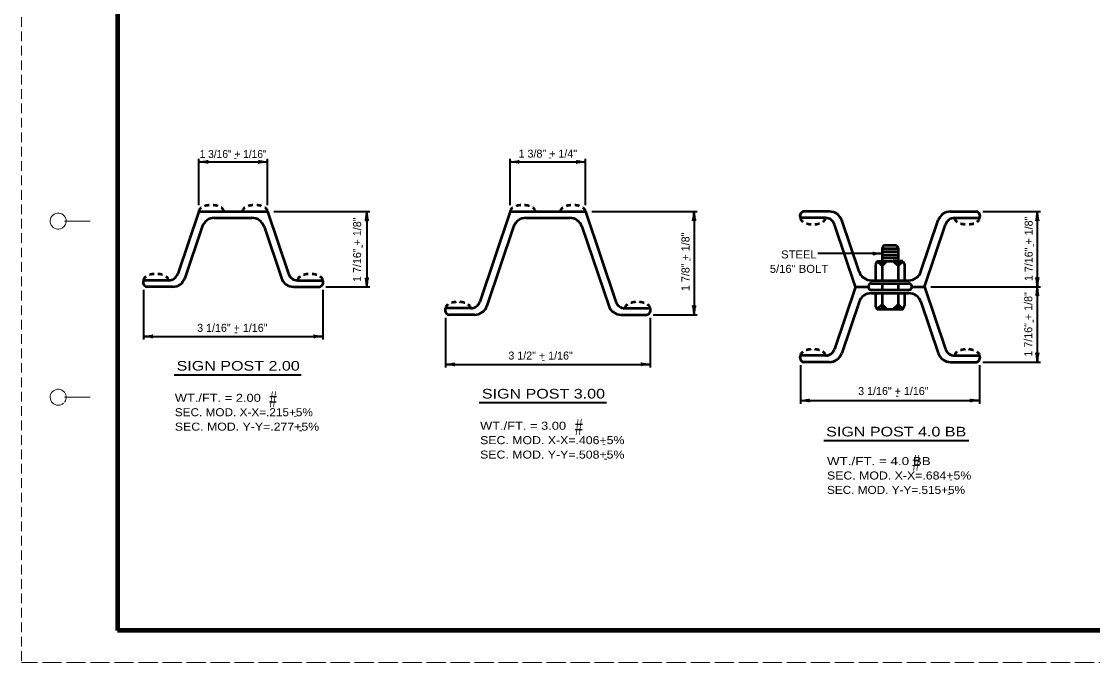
# Model space of a CAD drawing. Extents: x -2 to 678, y -1 to 439.
# Drawn here: x -1.8 to 332.9, y -0.7 to 199.5 of the extents above; entities that cross this region are included whole.
import ezdxf
from ezdxf.enums import TextEntityAlignment as Align

# ---------------------------------------------------------------- set-up
doc = ezdxf.new("R2010")
doc.units = 0
for name, pattern in [('LONG_DASHED', [7.5, 6, -1.5]), ('MEDIUM_DASHED', [4.5, 3, -1.5]), ('SHORT_DASHED', [2.7, 1.5, -1.2])]:
    doc.linetypes.add(name, pattern=pattern)
doc.layers.add('1', color=7, linetype='Continuous', lineweight=53)
doc.layers.add('61', color=7, linetype='Continuous', lineweight=35)

msp = doc.modelspace()

# ---------------------------------------------------------------- linework, layer by layer
at = {"layer": '1', "linetype": 'MEDIUM_DASHED', "lineweight": 13}
msp.add_line((-1.693, 439.301), (-1.753, -0.739), dxfattribs=at)
at = {"layer": '1', "lineweight": 35}
for p, q in [((53.628, 142.102), (53.628, 156.602)), ((53.628, 155.602), (75.128, 155.602)), ((75.128, 142.102), (75.128, 156.602)), ((150.929, 142.102), (150.929, 156.602)), ((150.929, 155.602), (174.429, 155.602)), ((174.429, 142.102), (174.429, 156.602)), ((77.128, 140.102), (107.128, 140.102)), ((106.128, 140.102), (106.128, 116.57)), ((176.429, 140.102), (209.37, 140.102)), ((208.37, 140.102), (208.37, 107.848)), ((298.576, 140.102), (316.576, 140.102)), ((267.076, 126.95), (247.023, 126.95)), ((36.378, 115.602), (36.378, 100.102)), ((92.378, 115.602), (92.378, 100.102)), ((93.378, 116.57), (107.128, 116.57)), ((282.326, 116.602), (316.576, 116.602)), ((195.62, 107.848), (209.37, 107.848)), ((130.738, 106.88), (130.738, 91.38)), ((194.62, 106.88), (194.62, 91.38)), ((36.378, 101.102), (92.378, 101.102)), ((130.738, 92.38), (194.62, 92.38)), ((241.576, 92.102), (241.576, 80.102)), ((297.576, 92.102), (297.576, 80.102)), ((298.576, 93.102), (316.576, 93.102)), ((241.576, 81.102), (297.576, 81.102))]:
    msp.add_line(p, q, dxfattribs=at)
at = {"layer": '1'}
for p, q in [((53.628, 140.102), (47.067, 120.644)), ((53.628, 140.102), (75.128, 140.102)), ((58.501, 138.102), (70.256, 138.102)), ((75.128, 140.102), (81.69, 120.644)), ((150.929, 140.102), (141.426, 111.922)), ((150.929, 140.102), (174.429, 140.102)), ((155.801, 138.102), (169.556, 138.102)), ((174.429, 140.102), (183.932, 111.922)), ((249.422, 138.102), (241.576, 138.102)), ((250.704, 140.102), (242.576, 140.102)), ((259.909, 121.324), (254.494, 137.38)), ((279.244, 121.324), (284.659, 137.38)), ((288.449, 140.102), (296.576, 140.102)), ((289.731, 138.102), (297.576, 138.102)), ((54.71, 135.38), (49.296, 119.324)), ((74.046, 135.38), (79.46, 119.324)), ((152.011, 135.38), (143.656, 110.602)), ((173.347, 135.38), (181.702, 110.602)), ((258.826, 116.602), (252.265, 136.061)), ((280.326, 116.602), (286.888, 136.061)), ((267.576, 129.602), (267.076, 128.602)), ((267.076, 128.602), (272.076, 128.602)), ((267.076, 127.602), (272.076, 127.602)), ((267.576, 129.602), (271.576, 129.602)), ((271.576, 129.602), (272.076, 128.602)), ((265.576, 124.602), (265.076, 123.602)), ((265.576, 124.602), (273.576, 124.602)), ((267.076, 126.602), (272.076, 126.602)), ((267.076, 125.602), (271.853, 125.602)), ((272.045, 125.602), (272.076, 125.602)), ((273.576, 124.602), (274.076, 123.602)), ((265.076, 123.602), (265.076, 118.602)), ((274.076, 123.602), (274.076, 118.602)), ((44.224, 118.602), (36.378, 118.602)), ((84.533, 118.602), (92.378, 118.602)), ((263.699, 118.602), (275.454, 118.602)), ((263.826, 117.602), (275.326, 117.602)), ((267.076, 117.602), (267.076, 115.602)), ((272.076, 117.602), (272.076, 115.602)), ((45.506, 116.602), (37.378, 116.602)), ((83.251, 116.602), (91.378, 116.602)), ((258.826, 116.602), (252.265, 97.144)), ((258.826, 116.602), (262.774, 116.602)), ((263.699, 114.602), (275.454, 114.602)), ((263.826, 115.602), (275.326, 115.602)), ((265.076, 114.602), (265.076, 110.602)), ((267.076, 114.602), (267.076, 109.602)), ((272.076, 114.602), (272.076, 109.602)), ((274.076, 114.602), (274.076, 110.602)), ((276.379, 116.602), (280.326, 116.602)), ((280.326, 116.602), (286.888, 97.144)), ((259.909, 111.88), (254.494, 95.824)), ((265.576, 109.602), (265.076, 110.602)), ((273.576, 109.602), (274.076, 110.602)), ((279.244, 111.88), (284.659, 95.824)), ((138.584, 109.88), (130.738, 109.88)), ((139.865, 107.88), (131.738, 107.88)), ((185.492, 107.88), (193.62, 107.88)), ((186.774, 109.88), (194.62, 109.88)), ((265.576, 109.602), (273.576, 109.602)), ((249.422, 95.102), (241.576, 95.102)), ((289.731, 95.102), (297.576, 95.102)), ((250.704, 93.102), (242.576, 93.102)), ((288.449, 93.102), (296.576, 93.102))]:
    msp.add_line(p, q, dxfattribs=at)
at = {"layer": '1', "lineweight": 40}
for p, q in [((45.917, 89.145), (85.62, 89.145)), ((141.276, 80.424), (180.98, 80.424)), ((248.895, 68.58), (294.191, 68.58))]:
    msp.add_line(p, q, dxfattribs=at)
at = {"layer": '1', "lineweight": 35}
msp.add_lwpolyline([(315.576, 140.102), (315.576, 116.602), (315.576, 93.102)], dxfattribs=at)
at = {"layer": '1'}
for points in [[(267.076, 128.602), (267.076, 124.602), (267.076, 118.602)], [(272.076, 128.602), (272.076, 124.602), (272.076, 118.602)]]:
    msp.add_lwpolyline(points, dxfattribs=at)
for points in [[(265.576, 124.602), (268.576, 124.602), (267.076, 123.102)], [(273.576, 124.602), (270.576, 124.602), (272.076, 123.102)], [(267.076, 111.102), (265.576, 109.602), (268.576, 109.602)], [(270.576, 109.602), (272.076, 111.102), (273.576, 109.602)]]:
    msp.add_lwpolyline(points, close=True, dxfattribs=at)
for centre, radius, start, end in [((58.501, 134.102), 4, 90, 161.36475), ((70.256, 134.102), 4, 18.63465, 90), ((155.801, 134.102), 4, 90, 161.36475), ((169.556, 134.102), 4, 18.63465, 90), ((242.841, 138.72), 1.408, 100.85533, 206.01456), ((249.422, 135.102), 3, 18.63464, 90), ((250.704, 136.102), 4, 18.63408, 90), ((288.449, 136.102), 4, 90, 161.36561), ((289.731, 135.102), 3, 90, 161.36548), ((296.311, 138.72), 1.408, 333.98544, 79.14467), ((44.224, 121.602), 3, 270, 341.36536), ((84.533, 121.602), 3, 198.63452, 270), ((263.699, 122.602), 4, 198.63525, 270), ((275.454, 122.602), 4, 270, 341.36535), ((37.643, 117.985), 1.408, 153.98544, 259.14467), ((45.506, 120.602), 4, 270, 341.36592), ((83.251, 120.602), 4, 198.63439, 270), ((91.113, 117.985), 1.408, 280.85533, 26.01456), ((263.775, 116.602), 1.001, 87.05408, 272.94592), ((275.378, 116.602), 1.001, 267.05408, 92.94592), ((263.699, 110.602), 4, 90, 161.36475), ((275.454, 110.602), 4, 18.63465, 90), ((138.584, 112.88), 3, 270, 341.36536), ((139.865, 111.88), 4, 270, 341.36592), ((185.492, 111.88), 4, 198.63439, 270), ((186.774, 112.88), 3, 198.63452, 270), ((132.003, 109.263), 1.408, 153.98544, 259.14467), ((193.355, 109.263), 1.408, 280.85533, 26.01456), ((249.422, 98.102), 3, 270, 341.36536), ((289.731, 98.102), 3, 198.63452, 270), ((242.841, 94.485), 1.408, 153.98544, 259.14467), ((250.704, 97.102), 4, 270, 341.36592), ((288.449, 97.102), 4, 198.63439, 270), ((296.311, 94.485), 1.408, 280.85533, 26.01456)]:
    msp.add_arc(centre, radius, start, end, dxfattribs=at)
at = {"layer": '1', "lineweight": 40}
for centre, major_axis, ratio, start_param, end_param in [((54.749, 155.391), (-1.756, 0.176), 0.07063, 3.1407148, 5.41811), ((54.72, 155.879), (-1.786, -0.156), 0.122415, 0.8963533, 3.1415927), ((74.037, 155.326), (1.786, 0.156), 0.122415, 0.8963533, 3.1415927), ((74.008, 155.814), (1.756, -0.176), 0.07063, 3.1407148, 5.41811), ((152.049, 155.391), (-1.756, 0.176), 0.07063, 3.1407148, 5.41811), ((152.049, 155.391), (-1.756, 0.176), 0.07063, 3.1407148, 5.41811), ((152.02, 155.879), (-1.786, -0.156), 0.122415, 0.8963533, 3.1415927), ((152.02, 155.879), (-1.786, -0.156), 0.122415, 0.8963533, 3.1415927), ((173.338, 155.326), (1.786, 0.156), 0.122415, 0.8963533, 3.1415927), ((173.308, 155.814), (1.756, -0.176), 0.07063, 3.1407148, 5.41811), ((105.917, 138.982), (0.176, 1.756), 0.07063, 3.1407148, 5.41811), ((105.917, 138.982), (0.176, 1.756), 0.07063, 3.1407148, 5.41811), ((106.405, 139.011), (-0.156, 1.786), 0.122415, 0.8963533, 3.1415927), ((106.405, 139.011), (-0.156, 1.786), 0.122415, 0.8963533, 3.1415927), ((208.158, 138.982), (0.176, 1.756), 0.07063, 3.1407148, 5.41811), ((208.158, 138.982), (0.176, 1.756), 0.07063, 3.1407148, 5.41811), ((208.646, 139.011), (-0.156, 1.786), 0.122415, 0.8963533, 3.1415927), ((208.646, 139.011), (-0.156, 1.786), 0.122415, 0.8963533, 3.1415927), ((315.365, 138.982), (0.176, 1.756), 0.07063, 3.1407148, 5.41811), ((315.853, 139.011), (-0.156, 1.786), 0.122415, 0.8963533, 3.1415927), ((265.956, 127.162), (1.756, -0.176), 0.07063, 3.1407148, 5.41811), ((265.985, 126.674), (1.786, 0.156), 0.122415, 0.8963533, 3.1415927), ((105.852, 117.662), (0.156, -1.786), 0.122415, 0.8963533, 3.1415927), ((106.34, 117.691), (-0.176, -1.756), 0.07063, 3.1407148, 5.41811), ((315.3, 117.693), (0.156, -1.786), 0.122415, 0.8963533, 3.1415927), ((315.3, 117.693), (0.156, -1.786), 0.122415, 0.8963533, 3.1415927), ((315.788, 117.723), (-0.176, -1.756), 0.07063, 3.1407148, 5.41811), ((315.788, 117.723), (-0.176, -1.756), 0.07063, 3.1407148, 5.41811), ((315.365, 115.482), (0.176, 1.756), 0.07063, 3.1407148, 5.41811), ((315.365, 115.482), (0.176, 1.756), 0.07063, 3.1407148, 5.41811), ((315.853, 115.511), (-0.156, 1.786), 0.122415, 0.8963533, 3.1415927), ((315.853, 115.511), (-0.156, 1.786), 0.122415, 0.8963533, 3.1415927), ((208.094, 108.94), (0.156, -1.786), 0.122415, 0.8963533, 3.1415927), ((208.582, 108.969), (-0.176, -1.756), 0.07063, 3.1407148, 5.41811), ((37.499, 100.891), (-1.756, 0.176), 0.07063, 3.1407148, 5.41811), ((37.499, 100.891), (-1.756, 0.176), 0.07063, 3.1407148, 5.41811), ((37.47, 101.379), (-1.786, -0.156), 0.122415, 0.8963533, 3.1415927), ((37.47, 101.379), (-1.786, -0.156), 0.122415, 0.8963533, 3.1415927), ((91.287, 100.826), (1.786, 0.156), 0.122415, 0.8963533, 3.1415927), ((91.258, 101.314), (1.756, -0.176), 0.07063, 3.1407148, 5.41811), ((315.3, 94.193), (0.156, -1.786), 0.122415, 0.8963533, 3.1415927), ((315.788, 94.223), (-0.176, -1.756), 0.07063, 3.1407148, 5.41811), ((131.858, 92.169), (-1.756, 0.176), 0.07063, 3.1407148, 5.41811), ((131.858, 92.169), (-1.756, 0.176), 0.07063, 3.1407148, 5.41811), ((131.829, 92.657), (-1.786, -0.156), 0.122415, 0.8963533, 3.1415927), ((131.829, 92.657), (-1.786, -0.156), 0.122415, 0.8963533, 3.1415927), ((193.529, 92.104), (1.786, 0.156), 0.122415, 0.8963533, 3.1415927), ((193.499, 92.592), (1.756, -0.176), 0.07063, 3.1407148, 5.41811), ((242.697, 80.891), (-1.756, 0.176), 0.07063, 3.1407148, 5.41811), ((242.697, 80.891), (-1.756, 0.176), 0.07063, 3.1407148, 5.41811), ((242.668, 81.379), (-1.786, -0.156), 0.122415, 0.8963533, 3.1415927), ((242.668, 81.379), (-1.786, -0.156), 0.122415, 0.8963533, 3.1415927), ((296.485, 80.826), (1.786, 0.156), 0.122415, 0.8963533, 3.1415927), ((296.456, 81.314), (1.756, -0.176), 0.07063, 3.1407148, 5.41811)]:
    msp.add_ellipse(centre, major_axis=major_axis, ratio=ratio, start_param=start_param, end_param=end_param, dxfattribs=at)
at = {"layer": '1', "linetype": 'SHORT_DASHED'}
for centre, major_axis, start_param, end_param in [((57.551, 140.102), (3.923, 0), 6.2831853, 9.424778), ((71.205, 140.102), (-3.923, 0), 3.1415927, 6.2831853), ((154.852, 140.102), (3.923, 0), 6.2831853, 9.424778), ((170.506, 140.102), (-3.923, 0), 3.1415927, 6.2831853), ((245.499, 138.102), (3.923, 0), 3.1415927, 6.2831853), ((293.653, 138.102), (-3.923, 0), 6.2831853, 9.424778), ((40.301, 118.602), (3.923, 0), 6.2831853, 9.424778), ((88.455, 118.602), (-3.923, 0), 3.1415927, 6.2831853), ((134.661, 109.88), (3.923, 0), 6.2831853, 9.424778), ((190.697, 109.88), (-3.923, 0), 3.1415927, 6.2831853), ((245.499, 95.102), (3.923, 0), 6.2831853, 9.424778), ((293.653, 95.102), (-3.923, 0), 3.1415927, 6.2831853)]:
    msp.add_ellipse(centre, major_axis=major_axis, ratio=0.50983, start_param=start_param, end_param=end_param, dxfattribs=at)
at = {"layer": '61', "lineweight": 13}
for p, q in [((11.727, 137.121), (19.727, 137.121)), ((11.747, 82.101), (19.727, 82.101))]:
    msp.add_line(p, q, dxfattribs=at)
at = {"layer": '61', "lineweight": 158}
msp.add_line((667.367, 9.261), (28.307, 9.281), dxfattribs=at)
at = {"layer": '61', "linetype": 'LONG_DASHED', "lineweight": 13}
msp.add_line((678.307, -0.719), (-1.753, -0.739), dxfattribs=at)
at = {"layer": '61', "lineweight": 158}
msp.add_lwpolyline([(667.347, 429.301), (28.307, 429.301), (28.307, 9.281)], dxfattribs=at)
at = {"layer": '61', "lineweight": 13}
for centre, start, end in [((9.724, 137.103), 322.67175, 321.71615), ((9.724, 82.103), 323.13009, 312.31439)]:
    msp.add_arc(centre, 2.5, start, end, dxfattribs=at)

# ---------------------------------------------------------------- texts
at = {"layer": '1'}
for s, height, width, p in [('1 3/16" + 1/16"', 2.5, 0.95, (64.383, 156.812)), ('STEEL', 2.5, 1.05, (241.134, 125.456)), ('5/16" BOLT', 2.5, 1.05, (241.134, 120.956)), ('SIGN POST 2.00', 3, 1.25, (65.958, 90.437)), ('#', 5, 0.65, (76.832, 78.968)), ('SIGN POST 3.00', 3, 1.25, (161.318, 81.715)), ('#', 5, 0.65, (172.342, 70.323)), ('SIGN POST 4.0 BB', 3, 1.25, (271.51, 69.871)), ('#', 5, 0.65, (277.769, 59.145))]:
    msp.add_text(s, height=height, dxfattribs=dict(at, width=width)).set_placement(p, align=Align.CENTER)
for s, p in [('1 3/8" + 1/4"', (162.683, 156.928)), ('-', (65.077, 155.737)), ('-', (163.378, 155.853)), ('3 1/16" + 1/16"', (64.123, 102.534)), ('-', (65.312, 101.243)), ('3 1/2" + 1/16"', (160.421, 93.874)), ('-', (161.243, 92.56)), ('3 1/16" + 1/16"', (270.619, 82.804)), ('-', (271.808, 81.514)), ('-', (83.841, 75.071)), ('-', (85.503, 70.638)), ('-', (180.263, 66.432)), ('-', (180.765, 61.81)), ('-', (288.593, 55.317)), ('-', (288.01, 50.712))]:
    msp.add_text(s, height=2.5, dxfattribs=at).set_placement(p, align=Align.CENTER)
for s, p in [('1 7/16" + 1/8"', (104.371, 128.173)), ('1 7/16" + 1/8"', (314.142, 128.44)), ('1 7/8" + 1/8"', (206.94, 124.4)), ('-', (105.631, 129.251)), ('-', (315.402, 129.519)), ('-', (208.071, 125.038)), ('1 7/16" + 1/8"', (314.011, 104.859)), ('-', (315.271, 105.937))]:
    msp.add_text(s, height=2.5, rotation=90, dxfattribs=at).set_placement(p, align=Align.CENTER)
for s, width, p in [('WT./FT. = 2.00', 1.2, (46.17, 80.682)), ('SEC. MOD. X-X=.215+5%', 1.1, (46.17, 76.182)), ('SEC. MOD. Y-Y=.277+5%', 1.15, (46.17, 71.682)), ('WT./FT. = 3.00', 1.2, (141.53, 71.96)), ('SEC. MOD. X-X=.406+5%', 1.15, (141.53, 67.46)), ('SEC. MOD. Y-Y=.508+5%', 1.15, (141.53, 62.96)), ('WT./FT. = 4.0 BB', 1.25, (249.886, 60.925)), ('SEC. MOD. X-X=.684+5%', 1.15, (249.886, 56.425)), ('SEC. MOD. Y-Y=.515+5%', 1.1, (249.886, 51.925))]:
    msp.add_text(s, height=2.5, dxfattribs=dict(at, width=width)).set_placement(p)

doc.saveas('drawing.dxf')
